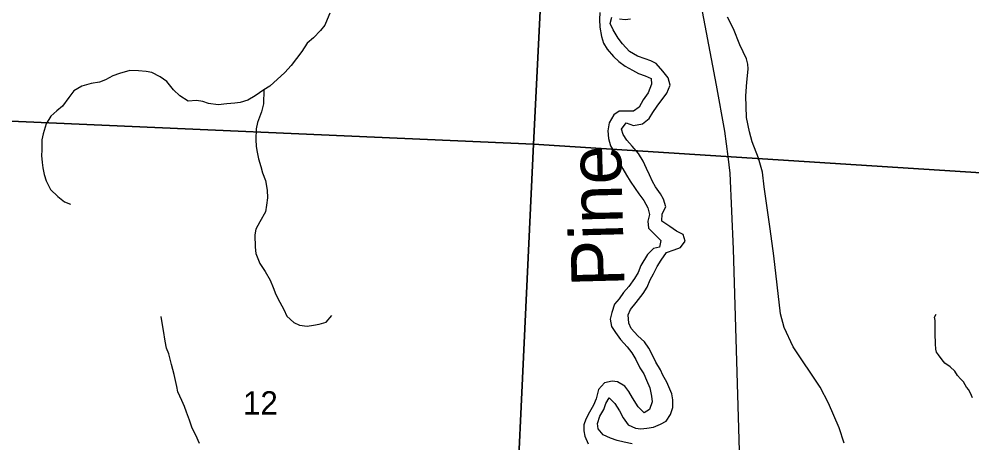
# Model space of a CAD drawing. Extents: x 0 to 44, y -23.8 to 22.
# Drawn here: x 3.565 to 5.27, y 18.084 to 18.843 of the extents above; entities that cross this region are included whole.
import ezdxf

# ---------------------------------------------------------------- set-up
doc = ezdxf.new("R2010")
doc.units = 0
for name, color, linetype in [('GM_X_Minor_River', 7, 'Continuous'), ('GM_X_Minor_River_Text', 7, 'Continuous'), ('GM_X_Rail_Line', 7, 'Continuous'), ('GM_X_Section', 7, 'Continuous'), ('GM_X_Section_Text', 7, 'Continuous'), ('GM_X_State_Route', 7, 'Continuous')]:
    doc.layers.add(name, color=color, linetype=linetype)

msp = doc.modelspace()

# ---------------------------------------------------------------- linework, layer by layer
at = {"layer": 'GM_X_Minor_River'}
for points in [[(4.1208, 18.8535), (4.1164, 18.8421), (4.1119, 18.8322), (4.1041, 18.8226), (4.092, 18.8092), (4.0807, 18.7996), (4.071, 18.7847), (4.0515, 18.7595), (4.0407, 18.7472), (4.0136, 18.7227), (4.0026, 18.7161), (3.9876, 18.7054), (3.9743, 18.6976), (3.9607, 18.6933), (3.9509, 18.6921), (3.9365, 18.6908), (3.9213, 18.6895), (3.9038, 18.6916), (3.8939, 18.695), (3.8821, 18.6968), (3.8673, 18.6958), (3.8524, 18.7052), (3.8413, 18.7161), (3.829, 18.7308), (3.8172, 18.7394), (3.8023, 18.7469), (3.792, 18.7487), (3.7784, 18.7504), (3.7632, 18.751), (3.7442, 18.7455), (3.7325, 18.7413), (3.7197, 18.7343), (3.7087, 18.7296), (3.6936, 18.7276), (3.6769, 18.7225), (3.663, 18.7144), (3.654, 18.7025), (3.6423, 18.6872), (3.6322, 18.6784), (3.6217, 18.6688), (3.6131, 18.6551), (3.6079, 18.6372), (3.6057, 18.6269), (3.6052, 18.6083), (3.6049, 18.5984), (3.6058, 18.5863), (3.607, 18.5768), (3.6094, 18.5643), (3.6133, 18.553), (3.6211, 18.5375), (3.6341, 18.5251), (3.6463, 18.5157), (3.657, 18.5116)], [(4.6045, 18.8546), (4.6037, 18.842), (4.6041, 18.8284), (4.6071, 18.8116), (4.6109, 18.7995), (4.6173, 18.7892), (4.6287, 18.7759), (4.6386, 18.7671), (4.6496, 18.7588), (4.6629, 18.7511), (4.6735, 18.7454), (4.6857, 18.7412), (4.696, 18.7367), (4.6971, 18.7264), (4.691, 18.7105), (4.6819, 18.6983), (4.675, 18.6854), (4.6644, 18.6782), (4.6389, 18.6782), (4.6294, 18.6714), (4.621, 18.6569), (4.6187, 18.6425), (4.6199, 18.6288), (4.6237, 18.6162), (4.6309, 18.6029), (4.6389, 18.5873), (4.6457, 18.5748), (4.6521, 18.5634), (4.6586, 18.5524), (4.6673, 18.5394), (4.6742, 18.5299), (4.6833, 18.5181), (4.6901, 18.5048), (4.6931, 18.493), (4.6905, 18.4809), (4.6916, 18.4683), (4.7011, 18.4588), (4.7136, 18.4466), (4.7113, 18.4345), (4.7003, 18.4318), (4.6897, 18.4212), (4.6775, 18.4014), (4.6729, 18.3889), (4.6665, 18.3786), (4.6562, 18.3638), (4.6467, 18.3532), (4.6391, 18.3422), (4.6307, 18.3323), (4.6257, 18.3175), (4.6227, 18.3057), (4.6254, 18.2924), (4.6322, 18.2817), (4.6413, 18.2692), (4.6531, 18.2563), (4.6614, 18.2456), (4.669, 18.2334), (4.6762, 18.2186), (4.6831, 18.208), (4.688, 18.1962), (4.6941, 18.1825), (4.6967, 18.168), (4.6982, 18.1574), (4.6933, 18.1441), (4.6838, 18.138), (4.6731, 18.1487), (4.6629, 18.1646), (4.6561, 18.176), (4.6492, 18.1859), (4.6359, 18.1935), (4.6264, 18.1947), (4.6127, 18.1917), (4.6021, 18.1795), (4.5975, 18.1632), (4.593, 18.1518), (4.5857, 18.1389), (4.5793, 18.1263), (4.5758, 18.1161), (4.5758, 18.1058), (4.5777, 18.0959), (4.5834, 18.0826)], [(4.7004, 18.1124), (4.713, 18.1177), (4.7229, 18.123), (4.7309, 18.1348), (4.735, 18.1477), (4.7351, 18.1614), (4.7332, 18.1721), (4.7244, 18.193), (4.7172, 18.2051), (4.713, 18.2147), (4.7047, 18.2283), (4.6986, 18.2413), (4.6922, 18.2538), (4.6842, 18.2648), (4.6724, 18.2755), (4.6603, 18.2888), (4.6565, 18.2983), (4.6553, 18.3131), (4.6592, 18.323), (4.6694, 18.3352), (4.6816, 18.3515), (4.6888, 18.3629), (4.6945, 18.3762), (4.7002, 18.3869), (4.7067, 18.3998), (4.7139, 18.4112), (4.7238, 18.4248), (4.7371, 18.4298), (4.7489, 18.4339), (4.7569, 18.445), (4.7535, 18.4571), (4.7417, 18.4632), (4.7299, 18.4712), (4.7151, 18.4811), (4.7159, 18.494), (4.7227, 18.5066), (4.7182, 18.5206), (4.7129, 18.5301), (4.7038, 18.5427), (4.6988, 18.5522), (4.6935, 18.564), (4.6878, 18.5754), (4.6821, 18.5883), (4.6738, 18.602), (4.6624, 18.6153), (4.6529, 18.626), (4.6461, 18.6359), (4.6434, 18.6458), (4.6514, 18.6568), (4.6647, 18.6522), (4.6807, 18.6552), (4.6928, 18.6647), (4.6989, 18.6754), (4.7069, 18.6871), (4.724, 18.7099), (4.7301, 18.7244), (4.7267, 18.7377), (4.7172, 18.7495), (4.7054, 18.7632), (4.6956, 18.7681), (4.6853, 18.7719), (4.6716, 18.7765), (4.6572, 18.7849), (4.645, 18.7986), (4.6374, 18.8088), (4.6279, 18.8237), (4.6226, 18.8347), (4.6257, 18.8461)], [(4.6397, 18.8434), (4.6496, 18.8419), (4.6591, 18.843)], [(4.0026, 18.7161), (4.0021, 18.6911), (3.9985, 18.677), (3.9918, 18.6579), (3.9889, 18.6461), (3.9887, 18.6272), (3.9892, 18.615), (3.9908, 18.6048), (3.9932, 18.5927), (3.9975, 18.5787), (4.0007, 18.5677), (4.0061, 18.5541), (4.009, 18.5366), (4.0095, 18.5226), (4.0077, 18.5097), (4.0056, 18.4975), (3.9955, 18.4799), (3.9884, 18.4666), (3.987, 18.4563), (3.9876, 18.4343), (3.9888, 18.4229), (3.9955, 18.4055), (4.0051, 18.3912), (4.014, 18.3753), (4.0198, 18.3621), (4.0245, 18.3496), (4.0314, 18.336), (4.0384, 18.3228), (4.0438, 18.3111), (4.0565, 18.2998), (4.0664, 18.295), (4.0805, 18.2928), (4.0918, 18.2948), (4.1021, 18.2965), (4.1145, 18.3004), (4.1247, 18.3122)], [(3.8878, 18.083), (3.8812, 18.0981), (3.8747, 18.1105), (3.8696, 18.1249), (3.8645, 18.1389), (3.8606, 18.1491), (3.8559, 18.1597), (3.849, 18.1756), (3.847, 18.1851), (3.8426, 18.2067), (3.8375, 18.2245), (3.8327, 18.2434), (3.8288, 18.2536), (3.8264, 18.2661), (3.8232, 18.2854), (3.8212, 18.2953), (3.8188, 18.3101)], [(5.2716, 18.1645), (5.2694, 18.1691), (5.265, 18.179), (5.2608, 18.184), (5.2582, 18.1883), (5.2553, 18.1936), (5.25, 18.199), (5.2448, 18.2048), (5.2399, 18.2124), (5.2317, 18.2201), (5.2219, 18.2271), (5.217, 18.2325), (5.2103, 18.2417), (5.2069, 18.2467), (5.2059, 18.2516), (5.2052, 18.2615), (5.2049, 18.268), (5.2046, 18.2733), (5.2047, 18.2794), (5.2043, 18.2851), (5.2046, 18.3029), (5.2035, 18.309), (5.2062, 18.3143)], [(4.662, 18.0824), (4.648, 18.0851), (4.6354, 18.0881), (4.6236, 18.0923), (4.6103, 18.0984), (4.6012, 18.1091), (4.6001, 18.119), (4.6043, 18.1319), (4.6115, 18.144), (4.6149, 18.1543), (4.621, 18.1649), (4.6313, 18.1543), (4.6393, 18.1414), (4.6461, 18.1292), (4.6552, 18.1166), (4.6681, 18.1102), (4.678, 18.109), (4.6883, 18.1105), (4.7004, 18.1124)]]:
    msp.add_lwpolyline(points, dxfattribs=at)
at = {"layer": 'GM_X_Rail_Line'}
msp.add_lwpolyline([(5.3735, 17.2591), (5.121, 17.4386), (5.0645, 17.4786), (5.0219, 17.5076), (5.0011, 17.5239), (4.9745, 17.5545), (4.9593, 17.581), (4.94, 17.6269), (4.8692, 17.8321), (4.8619, 17.8659), (4.8587, 17.9061), (4.8571, 17.9697), (4.8434, 18.4308), (4.8378, 18.5668), (4.8338, 18.5966), (4.8281, 18.6424), (4.8129, 18.7245), (4.7815, 18.8919)], dxfattribs=at)
at = {"layer": 'GM_X_Section'}
for points in [[(3.5517, 19.6956), (4.5363, 19.6324), (4.4853, 18.6191), (3.4822, 18.6631)], [(4.5363, 19.6324), (5.5628, 19.5693), (5.5009, 18.5537), (4.4853, 18.6191)], [(3.4822, 18.6631), (4.4853, 18.6191), (4.437, 17.5902), (3.7148, 17.6484), (3.6689, 17.7618), (3.473, 18.2548), (3.4582, 18.2946)], [(4.4853, 18.6191), (5.5009, 18.5537), (5.4377, 17.5257), (4.437, 17.5902)]]:
    msp.add_lwpolyline(points, close=True, dxfattribs=at)
at = {"layer": 'GM_X_State_Route'}
msp.add_lwpolyline([(5.0419, 18.0834), (5.0328, 18.1109), (5.0134, 18.1549), (4.9985, 18.1837), (4.9505, 18.256), (4.934, 18.2907), (4.9279, 18.3149), (4.9155, 18.4188), (4.909, 18.4676), (4.8986, 18.5426), (4.8957, 18.5687), (4.8886, 18.5939), (4.8772, 18.6228), (4.872, 18.6408), (4.8668, 18.6665), (4.8656, 18.7057), (4.8673, 18.7297), (4.8692, 18.7472), (4.8696, 18.7539), (4.8692, 18.7623), (4.867, 18.7719), (4.8552, 18.797), (4.8438, 18.8255), (4.8327, 18.8461)], dxfattribs=at)

# ---------------------------------------------------------------- texts
at = {"layer": 'GM_X_Minor_River_Text'}
msp.add_text('Pine', height=0.09469, rotation=91.493, dxfattribs=at).set_placement((4.6486, 18.3647))
at = {"layer": 'GM_X_Section_Text'}
msp.add_text('12', height=0.04186, rotation=0, dxfattribs=at).set_placement((3.9656, 18.1347))

doc.saveas('drawing.dxf')
